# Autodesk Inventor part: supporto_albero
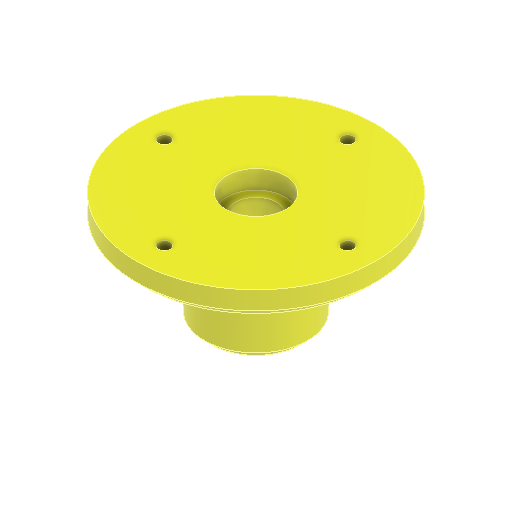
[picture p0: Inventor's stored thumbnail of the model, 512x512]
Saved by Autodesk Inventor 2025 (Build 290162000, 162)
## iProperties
Created: 2025-04
Part Number: supporto_albero
Material: Generico
Document SubType Name: Modeling
Designer: R5800u
Density: 1 g/cm^3
Appearance: Giallo
Author: R5800u
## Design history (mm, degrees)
sketch "Schizzo1"
  geometry: L1 (0, 0)-(28, 0); L2 (28, 0)-(28, 60); L3 (28, 60)-(0, 60); L4 (0, 60)-(0, 0); L5 (0, 14)-(28, 14); L6 (16.2, 14)-(16.2, 6.67); L7 (16.2, 6.67)-(16.2, 60); L8 (0, 58)-(16.2, 58); L9 (16.2, 14)-(16.2, 0); L10 (11.2, 14)-(11.2, 24); L11 (11.2, 24)-(16.2, 29.959); L12 (11.2, 24)-(11.2, 60); 8 further points
  constraints: 24 end point, 13 point on line, 8 perpendicular, 1 horizontal, 1 parallel, 1 vertical
  dimensions: "d0" = 28 distance of L1.start L1.end; "d1" = 60 distance of L1.end L2.end; "d2" = 14 distance between parallel lines of L1 L5; "d3" = 16.2 distance between parallel lines of L4 L7; "d4" = 2 distance between parallel lines of L8 L3; "d11" = 5 distance between parallel lines of L7 L10; "d13" = 10 distance of L10.start L10.end; "d15" = 40 deg angle of L7 L11
revolve "Rivoluzione1" sketch "Schizzo1" stored, may be unused: angle "d8" = 360 deg
sketch "Schizzo2"
  geometry: C1 r 28 at (0, 0) reference; C2 r 65 at (0, 0); 1 further point
  constraints: 1 centre point, 1 coincident
  dimensions: "d16" = 130 diameter of C2
extrude "Estrusione1" join sketch "Schizzo2" distance "d17" = 14; taper "d18" = 0 deg
sketch "Schizzo3"
  geometry: A1 r 50 centre (0, 0) between (50, 0) and (0, 50); 3 further points
  constraints: 4 point on circle, 1 centre point, 1 coincident
  dimensions: "d19" = 100 diameter of A1
hole "Foro1" sketch "Schizzo3" at (50, 0), (0, 50), (0, -50), (-50, 0) diameter "d20" = 6.4; stored, may be unused: countersink angle "d24" = 90 deg, drill point angle "d26" = 118 deg; dims "d21" = 6, "d22" = 10, "d23" = 7, "d25" = 8
fillet "Raccordo1" dims "d27" = 4
node "Modifica diretta1"
chamfer "Smusso1" distance "d31" = 2; stored, may be unused: second distance "d32" = 2, angle "d33" = 45 deg
sketch "Schizzo4"
  geometry: C1 r 10 at (0, 0); 1 further point
  constraints: 1 centre point, 1 coincident
  dimensions: "d34" = 20 diameter of C1
extrude "Estrusione2" cut sketch "Schizzo4" distance "d35" = 1.5; taper "d36" = 0 deg
fillet "Raccordo2" dims "d37" = 0.5
sketch "Schizzo6"
  geometry: L1 (-23.413, -2.751)-(-26.589, -2.749); L2 (-26.589, -2.749)-(-28.175, 0.001); L3 (-28.175, 0.001)-(-26.587, 2.751); L4 (-26.587, 2.751)-(-23.411, 2.749); L5 (-23.411, 2.749)-(-21.825, -0.001); L6 (-21.825, -0.001)-(-23.413, -2.751); C1 r 2.5 at (-25, 0) reference; 2 further points
  constraints: 12 end point, 1 coincident, 13 other
  dimensions: "d38" = 5.5 distance between parallel lines of L1 L4
extrude "Estrusione3" cut sketch "Schizzo6" stored distance "d39" = 1.5; taper "d40" = 0 deg
pattern_circular "Serie circolare1" dims angle "d42" = 360 deg
chamfer "Smusso2" distance "d44" = 1; stored, may be unused: second distance "d45" = 2, angle "d46" = 45 deg
sketch "Schizzo7"
  geometry: C1 r 8 at (0, 0); 1 further point
  constraints: 1 centre point, 1 coincident
  dimensions: "d47" = 16 diameter of C1
extrude "Estrusione4" cut sketch "Schizzo7" distance "d48" = 5.1; taper "d49" = 0 deg
node "Solido1"
feature "Scala1"
other parameters: "d28" = 5
